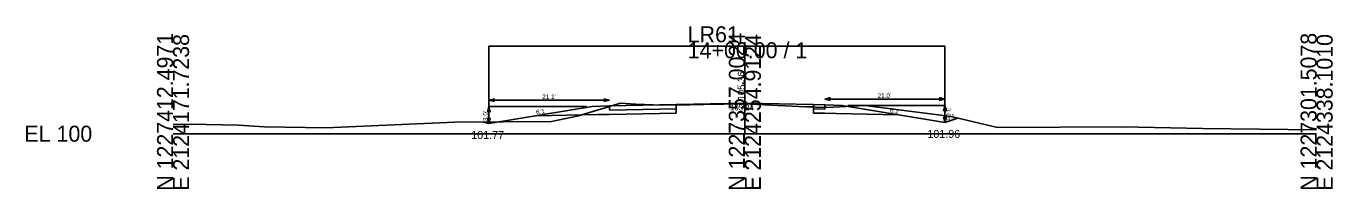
# Model space of a CAD drawing. Extents: x 2126751 to 2128979, y 1225108 to 1234639.
# Drawn here: x 2127750.9 to 2127979.4, y 1229107.5 to 1229136.1 of the extents above; entities that cross this region are included whole.
import ezdxf

# ---------------------------------------------------------------- set-up
doc = ezdxf.new("R2010")
doc.units = 0
for name, color, linetype in [('XS_CELL', 7, 'Continuous'), ('XS_M_DITCH', 7, 'Continuous'), ('XS_P_FINISHED_GRADE', 7, 'Continuous'), ('XS_P_FINISHED_GRADE_ELEV_TX', 7, 'Continuous'), ('XS_P_SUBGRADE_GRANULAR', 7, 'Continuous'), ('XS_P_SUBGRADE_LEVELING', 7, 'Continuous'), ('XS_P_SUBGRADE_PAVEMENT', 7, 'Continuous'), ('XS_P_TX_CLEARZONE', 7, 'Continuous'), ('XS_P_TX_DCH', 7, 'Continuous'), ('XS_P_TX_FS_BS', 7, 'Continuous'), ('XS_X_GROUND', 7, 'Continuous'), ('XS_X_GROUND_TX', 7, 'Continuous')]:
    doc.layers.add(name, color=color, linetype=linetype)

msp = doc.modelspace()

# ---------------------------------------------------------------- linework, layer by layer
at = {"layer": 'XS_CELL'}
for p, q in [((2127876.61, 1229117.21), (2127876.61, 1229133.25)), ((2127776.61, 1229117.21), (2127876.61, 1229117.21)), ((2127876.61, 1229117.21), (2127976.61, 1229117.21))]:
    msp.add_line(p, q, dxfattribs=at)
at = {"layer": 'XS_M_DITCH'}
for p, q in [((2127831.84, 1229118.98), (2127831.84, 1229132.57)), ((2127831.84, 1229132.57), (2127911.61, 1229132.57)), ((2127911.61, 1229132.57), (2127911.61, 1229119.17))]:
    msp.add_line(p, q, dxfattribs=at)
at = {"layer": 'XS_P_FINISHED_GRADE'}
for p, q in [((2127849.93, 1229121.98), (2127831.84, 1229118.98)), ((2127852.95, 1229122.1), (2127849.93, 1229121.98)), ((2127864.61, 1229122.33), (2127852.95, 1229122.1)), ((2127864.61, 1229122.33), (2127876.61, 1229122.57)), ((2127876.61, 1229122.57), (2127888.61, 1229122.33)), ((2127888.61, 1229122.33), (2127890.61, 1229122.29)), ((2127890.61, 1229122.29), (2127893.61, 1229122.17)), ((2127893.61, 1229122.17), (2127911.61, 1229119.17)), ((2127831.84, 1229118.98), (2127830.99, 1229119.26)), ((2127911.61, 1229119.17), (2127913.88, 1229119.93))]:
    msp.add_line(p, q, dxfattribs=at)
at = {"layer": 'XS_P_SUBGRADE_GRANULAR'}
for p, q in [((2127864.61, 1229120.83), (2127864.61, 1229121.58)), ((2127888.61, 1229120.83), (2127888.61, 1229121.58)), ((2127850.95, 1229120.56), (2127840.05, 1229120.34)), ((2127852.95, 1229120.6), (2127850.95, 1229120.56)), ((2127864.61, 1229120.83), (2127852.95, 1229120.6)), ((2127888.61, 1229120.83), (2127890.61, 1229120.79)), ((2127890.61, 1229120.79), (2127892.61, 1229120.75)), ((2127892.61, 1229120.75), (2127903.43, 1229120.54))]:
    msp.add_line(p, q, dxfattribs=at)
at = {"layer": 'XS_P_SUBGRADE_LEVELING'}
for p, q in [((2127864.61, 1229122.33), (2127864.61, 1229122.24)), ((2127864.61, 1229122.24), (2127869.45, 1229122.32)), ((2127869.45, 1229122.32), (2127876.44, 1229122.46)), ((2127876.44, 1229122.46), (2127887.29, 1229121.95)), ((2127887.29, 1229121.95), (2127888.61, 1229121.9)), ((2127888.61, 1229122.33), (2127888.61, 1229121.9))]:
    msp.add_line(p, q, dxfattribs=at)
at = {"layer": 'XS_P_SUBGRADE_PAVEMENT'}
for p, q in [((2127852.95, 1229121.35), (2127852.95, 1229122.1)), ((2127864.61, 1229121.58), (2127852.95, 1229121.35)), ((2127864.61, 1229121.58), (2127864.61, 1229122.24)), ((2127888.61, 1229121.58), (2127888.61, 1229121.9)), ((2127888.61, 1229121.58), (2127890.61, 1229121.54)), ((2127890.61, 1229121.54), (2127890.61, 1229122.29))]:
    msp.add_line(p, q, dxfattribs=at)
at = {"layer": 'XS_P_TX_CLEARZONE'}
for p, q in [((2127831.84, 1229121.98), (2127831.58, 1229120.98)), ((2127831.84, 1229123.1), (2127832.84, 1229123.35)), ((2127831.84, 1229123.1), (2127832.84, 1229122.85)), ((2127852.95, 1229123.1), (2127831.84, 1229123.1)), ((2127831.84, 1229121.98), (2127832.09, 1229120.98)), ((2127831.84, 1229121.98), (2127831.84, 1229118.98)), ((2127848.93, 1229121.98), (2127831.84, 1229121.98)), ((2127852.95, 1229123.1), (2127851.95, 1229123.35)), ((2127852.95, 1229123.1), (2127851.95, 1229122.85)), ((2127890.61, 1229123.29), (2127891.61, 1229123.54)), ((2127890.61, 1229123.29), (2127891.61, 1229123.04)), ((2127890.61, 1229123.29), (2127911.61, 1229123.29)), ((2127894.61, 1229122.17), (2127911.61, 1229122.17)), ((2127911.61, 1229123.29), (2127910.61, 1229123.54)), ((2127911.61, 1229123.29), (2127910.61, 1229123.04)), ((2127911.61, 1229122.17), (2127911.36, 1229121.17)), ((2127911.61, 1229122.17), (2127911.61, 1229119.17)), ((2127911.61, 1229122.17), (2127911.86, 1229121.17)), ((2127831.84, 1229118.98), (2127831.58, 1229119.98)), ((2127831.84, 1229118.98), (2127832.09, 1229119.98)), ((2127911.61, 1229119.17), (2127911.36, 1229120.17)), ((2127911.61, 1229119.17), (2127911.86, 1229120.17))]:
    msp.add_line(p, q, dxfattribs=at)
at = {"layer": 'XS_X_GROUND'}
for p, q in [((2127847.49, 1229120.36), (2127854.84, 1229122.56)), ((2127854.84, 1229122.56), (2127857.48, 1229122.42)), ((2127857.48, 1229122.42), (2127862.13, 1229122.2)), ((2127862.13, 1229122.2), (2127869.45, 1229122.32)), ((2127869.45, 1229122.32), (2127876.44, 1229122.46)), ((2127876.44, 1229122.46), (2127887.29, 1229121.95)), ((2127887.29, 1229121.95), (2127890.8, 1229121.82)), ((2127890.8, 1229121.82), (2127892.12, 1229121.88)), ((2127892.12, 1229121.88), (2127897.61, 1229122.15)), ((2127897.61, 1229122.15), (2127912.7, 1229120.21)), ((2127803.31, 1229118.25), (2127825.89, 1229119.22)), ((2127825.89, 1229119.22), (2127842.79, 1229119.36)), ((2127842.79, 1229119.36), (2127847.49, 1229120.36)), ((2127912.7, 1229120.21), (2127920.78, 1229118.3)), ((2127776.61, 1229118.84), (2127779.63, 1229118.87)), ((2127779.63, 1229118.87), (2127788.03, 1229118.71)), ((2127788.03, 1229118.71), (2127792.63, 1229118.44)), ((2127792.63, 1229118.44), (2127803.31, 1229118.25)), ((2127920.78, 1229118.3), (2127942.64, 1229118.43)), ((2127942.64, 1229118.43), (2127956.66, 1229118.1)), ((2127956.66, 1229118.1), (2127976.61, 1229117.91))]:
    msp.add_line(p, q, dxfattribs=at)

# ---------------------------------------------------------------- texts
at = {"layer": 'XS_CELL'}
for s, p in [('LR61', (2127866.61, 1229133.25)), ('14+00.00 / 1', (2127866.61, 1229130.45)), ('EL 100', (2127750.61, 1229115.81))]:
    msp.add_text(s, height=2.8, dxfattribs=at).set_placement(p)
for s, p in [('N 1227412.4971', (2127776.61, 1229107.21)), ('E 2124171.7238', (2127779.41, 1229107.21)), ('N 1227357.0024', (2127876.61, 1229107.21)), ('E 2124254.9124', (2127879.41, 1229107.21)), ('N 1227301.5078', (2127976.61, 1229107.21)), ('E 2124338.1010', (2127979.41, 1229107.21))]:
    msp.add_text(s, height=2.8, rotation=90, dxfattribs=at).set_placement(p)
at = {"layer": 'XS_P_FINISHED_GRADE_ELEV_TX'}
msp.add_text(' 105.36', height=1.25, rotation=90, dxfattribs=at).set_placement((2127876.61, 1229122.57))
at = {"layer": 'XS_P_TX_CLEARZONE'}
for s, p in [("21.1'", (2127841.18, 1229123.3)), ("21.0'", (2127899.82, 1229123.49))]:
    msp.add_text(s, height=0.8, dxfattribs=at).set_placement(p)
for rotation, p in [(270, (2127911.81, 1229121.7)), (90, (2127831.63, 1229119.45))]:
    msp.add_text("3.0'", height=0.8, rotation=rotation, dxfattribs=at).set_placement(p)
at = {"layer": 'XS_P_TX_DCH'}
for s, p in [('101.77', (2127828.77, 1229116.28)), ('101.96', (2127908.54, 1229116.47))]:
    msp.add_text(s, height=1.4, dxfattribs=at).set_placement(p)
at = {"layer": 'XS_P_TX_FS_BS'}
for s, rotation, p in [('6:1', 9.412, (2127840.16, 1229120.56)), ('6:1', 350.5377, (2127901.95, 1229120.98)), ('3:1', 18.4349, (2127912.04, 1229119.53))]:
    msp.add_text(s, height=0.8, rotation=rotation, dxfattribs=at).set_placement(p)
at = {"layer": 'XS_X_GROUND_TX'}
msp.add_text('105.24', height=1, dxfattribs=at).set_placement((2127874.05, 1229121.29))

doc.saveas('drawing.dxf')
